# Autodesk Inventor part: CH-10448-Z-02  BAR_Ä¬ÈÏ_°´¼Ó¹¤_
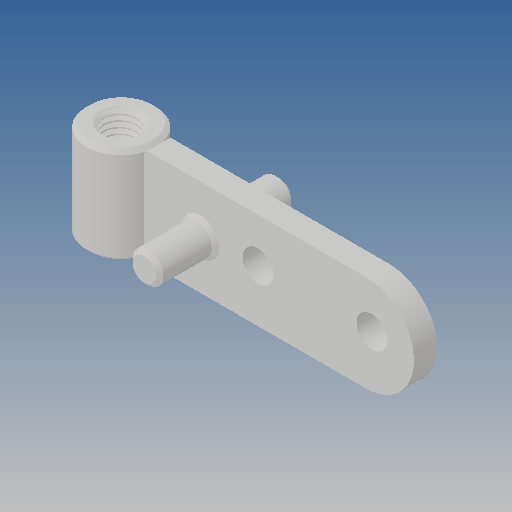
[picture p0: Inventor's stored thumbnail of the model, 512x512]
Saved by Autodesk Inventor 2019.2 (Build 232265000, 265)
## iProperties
Created: 2010-06
Part Number: CH-10448-Z-02  BAR_Ä¬ÈÏ_°´¼Ó¹¤_
Material: Ogólny
Document SubType Name: Modeling
Designer: CADENGINEERING4
Density: 1 g/cm^3
Appearance: Domyślna
Author: CADENGINEERING4
Revision Number: ÈÎºÎ
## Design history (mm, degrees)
feature "NONE"
feature "NONE:1"
feature "NONE:2"
feature "NONE:3"
feature "NONE:4"
feature "NONE:5"
feature "NONE:6"
feature "NONE:7"
feature "NONE:8"
feature "NONE:9"
feature "NONE:10"
node "Bryła1"
node "Bryła2"
node "Bryła3"
node "Bryła4"
node "Bryła5"
node "Bryła6"
node "Bryła7"
node "Bryła8"
node "Bryła9"
node "Bryła10"
node "Bryła11"
